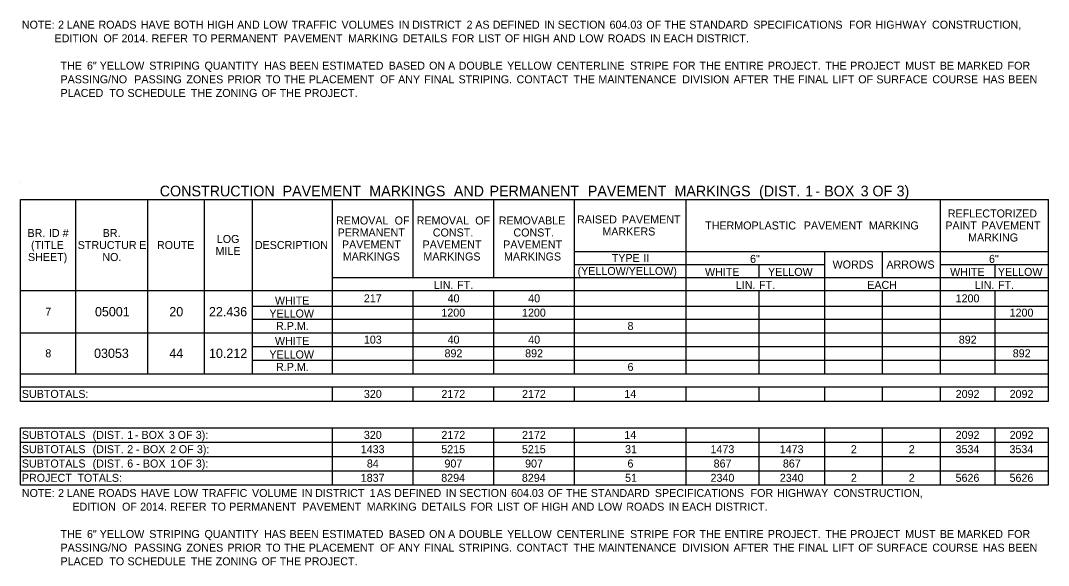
# Model space of a CAD drawing. Extents: x 542596 to 1930787, y -1948294 to 596640.
# Drawn here: x 557797 to 558568, y -1947009 to -1946601 of the extents above; entities that cross this region are included whole.
import ezdxf

# ---------------------------------------------------------------- set-up
doc = ezdxf.new("R2010")
doc.units = 0
doc.layers.add('Default', color=7, linetype='Continuous')

msp = doc.modelspace()

# ---------------------------------------------------------------- linework, layer by layer
at = {"layer": 'Default'}
for p, q in [((557797.21, -1946722.08), (557797.21, -1946722.08)), ((557797.21, -1946734.75), (558567.95, -1946734.75)), ((557797.21, -1946885.88), (557797.21, -1946734.75)), ((557838.65, -1946865.4), (557838.65, -1946734.75)), ((557892.76, -1946865.4), (557892.76, -1946734.75)), ((557935.18, -1946865.4), (557935.18, -1946734.75)), ((557971.25, -1946865.4), (557971.25, -1946734.75)), ((558031.21, -1946865.4), (558031.21, -1946734.75)), ((558091.66, -1946793.25), (558091.66, -1946734.75)), ((558152.11, -1946793.25), (558152.11, -1946734.75)), ((558212.56, -1946865.4), (558212.56, -1946734.75)), ((558296.41, -1946865.4), (558296.41, -1946734.75)), ((558487.03, -1946865.4), (558487.03, -1946734.75)), ((558567.95, -1946875.15), (558567.95, -1946734.75)), ((558212.56, -1946773.75), (558567.95, -1946773.75)), ((558400.25, -1946865.4), (558400.25, -1946773.75)), ((558400.25, -1946865.4), (558400.25, -1946773.75)), ((558443.64, -1946793.25), (558443.64, -1946773.75)), ((558212.56, -1946783.5), (558400.25, -1946783.5)), ((558351.01, -1946793.25), (558351.01, -1946783.5)), ((558487.03, -1946783.5), (558567.95, -1946783.5)), ((558527.98, -1946793.25), (558527.98, -1946783.5)), ((558031.21, -1946793.25), (558567.95, -1946793.25)), ((558212.56, -1946865.4), (558212.56, -1946793.25)), ((558400.25, -1946793.25), (558567.95, -1946793.25)), ((557797.21, -1946803), (558567.95, -1946803)), ((557971.25, -1946803), (558296.41, -1946803)), ((557971.25, -1946865.4), (557971.25, -1946803)), ((558031.21, -1946824.45), (558031.21, -1946803)), ((558091.66, -1946865.4), (558091.66, -1946803)), ((558091.66, -1946865.4), (558091.66, -1946803)), ((558152.11, -1946865.4), (558152.11, -1946803)), ((558152.11, -1946865.4), (558152.11, -1946803)), ((558296.41, -1946865.4), (558296.41, -1946803)), ((558351.01, -1946803), (558567.95, -1946803)), ((558351.01, -1946834.69), (558351.01, -1946803)), ((558351.01, -1946865.4), (558351.01, -1946803)), ((558443.64, -1946865.4), (558443.64, -1946803)), ((558443.64, -1946865.4), (558443.64, -1946803)), ((558487.03, -1946865.4), (558487.03, -1946803)), ((558527.98, -1946865.4), (558527.98, -1946803)), ((558527.98, -1946865.4), (558527.98, -1946803)), ((557971.25, -1946814.7), (558567.95, -1946814.7)), ((557971.25, -1946824.45), (558567.95, -1946824.45)), ((557797.21, -1946834.69), (558567.95, -1946834.69)), ((557971.25, -1946834.69), (558296.41, -1946834.69)), ((558031.21, -1946855.16), (558031.21, -1946834.69)), ((558351.01, -1946834.69), (558567.95, -1946834.69)), ((557971.25, -1946844.93), (558567.95, -1946844.93)), ((557971.25, -1946855.16), (558567.95, -1946855.16)), ((557797.21, -1946865.4), (558567.95, -1946865.4)), ((557797.21, -1946875.15), (558567.95, -1946875.15)), ((557797.21, -1946875.15), (558567.95, -1946875.15)), ((558031.21, -1946885.88), (558031.21, -1946875.15)), ((558031.21, -1946885.88), (558031.21, -1946875.15)), ((558091.66, -1946885.88), (558091.66, -1946875.15)), ((558091.66, -1946885.88), (558091.66, -1946875.15)), ((558152.11, -1946885.88), (558152.11, -1946875.15)), ((558152.11, -1946885.88), (558152.11, -1946875.15)), ((558212.56, -1946885.88), (558212.56, -1946875.15)), ((558212.56, -1946885.88), (558212.56, -1946875.15)), ((558296.41, -1946885.88), (558296.41, -1946875.15)), ((558296.41, -1946885.88), (558296.41, -1946875.15)), ((558351.01, -1946885.88), (558351.01, -1946875.15)), ((558351.01, -1946885.88), (558351.01, -1946875.15)), ((558400.25, -1946885.88), (558400.25, -1946875.15)), ((558400.25, -1946885.88), (558400.25, -1946875.15)), ((558443.64, -1946885.88), (558443.64, -1946875.15)), ((558443.64, -1946885.88), (558443.64, -1946875.15)), ((558487.03, -1946885.88), (558487.03, -1946875.15)), ((558487.03, -1946885.88), (558487.03, -1946875.15)), ((558527.98, -1946885.88), (558527.98, -1946875.15)), ((558527.98, -1946885.88), (558527.98, -1946875.15)), ((558567.95, -1946885.88), (558567.95, -1946875.15)), ((557797.21, -1946885.88), (558567.95, -1946885.88)), ((557797.21, -1946905.86), (558567.95, -1946905.86)), ((557797.21, -1946905.86), (558567.95, -1946905.86)), ((557797.21, -1946948.76), (557797.21, -1946905.86)), ((558031.21, -1946948.76), (558031.21, -1946905.86)), ((558031.21, -1946948.76), (558031.21, -1946905.86)), ((558091.66, -1946948.76), (558091.66, -1946905.86)), ((558091.66, -1946948.76), (558091.66, -1946905.86)), ((558152.11, -1946948.76), (558152.11, -1946905.86)), ((558152.11, -1946948.76), (558152.11, -1946905.86)), ((558212.56, -1946948.76), (558212.56, -1946905.86)), ((558212.56, -1946948.76), (558212.56, -1946905.86)), ((558296.41, -1946948.76), (558296.41, -1946905.86)), ((558296.41, -1946948.76), (558296.41, -1946905.86)), ((558351.01, -1946948.76), (558351.01, -1946905.86)), ((558351.01, -1946948.76), (558351.01, -1946905.86)), ((558400.25, -1946948.76), (558400.25, -1946905.86)), ((558400.25, -1946948.76), (558400.25, -1946905.86)), ((558443.64, -1946948.76), (558443.64, -1946905.86)), ((558443.64, -1946948.76), (558443.64, -1946905.86)), ((558487.03, -1946948.76), (558487.03, -1946905.86)), ((558487.03, -1946948.76), (558487.03, -1946905.86)), ((558527.98, -1946948.76), (558527.98, -1946905.86)), ((558527.98, -1946948.76), (558527.98, -1946905.86)), ((558567.95, -1946948.76), (558567.95, -1946905.86)), ((557797.21, -1946916.59), (558567.95, -1946916.59)), ((557797.21, -1946927.31), (558567.95, -1946927.31)), ((557797.21, -1946938.04), (558567.95, -1946938.04)), ((557797.21, -1946948.76), (558567.95, -1946948.76))]:
    msp.add_line(p, q, dxfattribs=at)

# ---------------------------------------------------------------- texts
for s, height, p in [('NOTE:', 6, (557798.19, -1946606.73)), (' 2', 6, (557823.08, -1946606.73)), (' LANE', 6, (557829.62, -1946606.73)), (' ROADS', 6, (557853.4, -1946606.73)), (' HAVE', 6, (557885.11, -1946606.73)), (' BOTH', 6, (557909.82, -1946606.73)), (' HIGH', 6, (557934.76, -1946606.73)), (' AND', 6, (557957.37, -1946606.73)), (' LOW', 6, (557976.95, -1946606.73)), (' TRAFFIC', 6, (557998.28, -1946606.73)), (' VOLUMES', 6, (558035.67, -1946606.73)), (' IN', 6, (558078.56, -1946606.73)), (' DISTRICT', 6, (558088.58, -1946606.73)), (' 2', 6, (558129.4, -1946606.73)), (' AS', 6, (558135.94, -1946606.73)), (' DEFINED', 6, (558149.01, -1946606.73)), (' IN', 6, (558187.69, -1946606.73)), (' SECTION', 6, (558197.72, -1946606.73)), (' 604.03', 6, (558236.63, -1946606.73)), (' OF', 6, (558264.2, -1946606.73)), (' THE', 6, (558277.79, -1946606.73)), (' STANDARD', 6, (558296.44, -1946606.73)), (' SPECIFICATIONS', 6, (558344.44, -1946606.73)), (' FOR', 6, (558416.21, -1946606.73)), (' HIGHWAY', 6, (558436.12, -1946606.73)), (' CONSTRUCTION,', 6, (558478.44, -1946606.73)), ('           EDITION', 6, (557798.19, -1946616.97)), (' OF', 6, (557857.11, -1946616.97)), (' 2014.', 6, (557870.7, -1946616.97)), (' REFER', 6, (557893.26, -1946616.97)), (' TO', 6, (557923.89, -1946616.97)), (' PERMANENT', 6, (557937.49, -1946616.97)), (' PAVEMENT', 6, (557992.29, -1946616.97)), (' MARKING', 6, (558040.57, -1946616.97)), (' DETAILS', 6, (558081.5, -1946616.97)), (' FOR', 6, (558118.33, -1946616.97)), (' LIST', 6, (558138.24, -1946616.97)), (' OF', 6, (558158.11, -1946616.97)), (' HIGH', 6, (558171.69, -1946616.97)), (' AND', 6, (558194.3, -1946616.97)), (' LOW', 6, (558213.89, -1946616.97)), (' ROADS', 6, (558235.21, -1946616.97)), (' IN', 6, (558266.92, -1946616.97)), (' EACH', 6, (558276.94, -1946616.97)), (' DISTRICT.', 6, (558301.89, -1946616.97)), ('             THE', 6, (557798.19, -1946637.45)), (' 6"', 6, (557844.77, -1946637.45)), (' YELLOW', 6, (557854.34, -1946637.45)), (' STRIPING', 6, (557891.51, -1946637.45)), (' QUANTITY', 6, (557932.91, -1946637.45)), (' HAS', 6, (557977.56, -1946637.45)), (' BEEN', 6, (557996.69, -1946637.45)), (' ESTIMATED', 6, (558021.17, -1946637.45)), (' BASED', 6, (558071.03, -1946637.45)), (' ON', 6, (558101.33, -1946637.45)), (' A', 6, (558115.55, -1946637.45)), (' DOUBLE', 6, (558123.49, -1946637.45)), (' YELLOW', 6, (558159.84, -1946637.45)), (' CENTERLINE', 6, (558197.01, -1946637.45)), (' STRIPE', 6, (558252, -1946637.45)), (' FOR', 6, (558284.17, -1946637.45)), (' THE', 6, (558304.08, -1946637.45)), (' ENTIRE', 6, (558322.73, -1946637.45)), (' PROJECT.', 6, (558355.35, -1946637.45)), (' THE', 6, (558398.41, -1946637.45)), (' PROJECT', 6, (558417.06, -1946637.45)), (' MUST', 6, (558458.35, -1946637.45)), (' BE', 6, (558484.26, -1946637.45)), (' MARKED', 6, (558497.33, -1946637.45)), (' FOR', 6, (558535.08, -1946637.45)), ('             PASSING/NO', 6, (557798.19, -1946647.68)), (' PASSING', 6, (557880.25, -1946647.68)), (' ZONES', 6, (557919.33, -1946647.68)), (' PRIOR', 6, (557950.1, -1946647.68)), (' TO', 6, (557978.87, -1946647.68)), (' THE', 6, (557992.47, -1946647.68)), (' PLACEMENT', 6, (558011.12, -1946647.68)), (' OF', 6, (558064.52, -1946647.68)), (' ANY', 6, (558078.11, -1946647.68)), (' FINAL', 6, (558097.61, -1946647.68)), (' STRIPING.', 6, (558123.4, -1946647.68)), (' CONTACT', 6, (558166.92, -1946647.68)), (' THE', 6, (558209.6, -1946647.68)), (' MAINTENANCE', 6, (558228.25, -1946647.68)), (' DIVISION', 6, (558291.15, -1946647.68)), (' AFTER', 6, (558329.6, -1946647.68)), (' THE', 6, (558359.29, -1946647.68)), (' FINAL', 6, (558377.94, -1946647.68)), (' LIFT', 6, (558403.73, -1946647.68)), (' OF', 6, (558423.12, -1946647.68)), (' SURFACE', 6, (558436.71, -1946647.68)), (' COURSE', 6, (558478.65, -1946647.68)), (' HAS', 6, (558516.4, -1946647.68)), (' BEEN', 6, (558535.53, -1946647.68)), ('             PLACED', 6, (557798.19, -1946657.92)), (' TO', 6, (557861.55, -1946657.92)), (' SCHEDULE', 6, (557875.15, -1946657.92)), (' THE', 6, (557922.68, -1946657.92)), (' ZONING', 6, (557941.33, -1946657.92)), (' OF', 6, (557975.74, -1946657.92)), (' THE', 6, (557989.32, -1946657.92)), (' PROJECT.', 6, (558007.97, -1946657.92)), ('CONSTRUCTION', 8, (557901.59, -1946732.41)), (' PAVEMENT', 8, (557990.74, -1946732.41)), (' MARKINGS', 8, (558055.73, -1946732.41)), (' AND', 8, (558119.14, -1946732.41)), (' PERMANENT', 8, (558145.91, -1946732.41)), (' PAVEMENT', 8, (558219.59, -1946732.41)), (' MARKINGS', 8, (558284.57, -1946732.41)), (' (DIST.', 8, (558347.99, -1946732.41)), (' 1', 8, (558382.61, -1946732.41)), (' BOX', 8, (558396.86, -1946732.41)), (' 3', 8, (558424.18, -1946732.41)), (' OF', 8, (558433.01, -1946732.41)), (' 3)', 8, (558451.12, -1946732.41)), (' -', 8, (558390.12, -1946732.41)), ('REFLECTORIZED', 6, (558492.53, -1946748.25)), ('REMOVAL', 6, (558033.81, -1946753.5)), (' OF', 6, (558075.48, -1946753.5)), ('REMOVAL', 6, (558094.26, -1946753.5)), (' OF', 6, (558135.93, -1946753.5)), ('REMOVABLE', 6, (558155.76, -1946753.5)), ('RAISED', 6, (558214.49, -1946752.75)), (' PAVEMENT', 6, (558245.75, -1946752.75)), ('THERMOPLASTIC', 6, (558310.53, -1946757.25)), (' PAVEMENT', 6, (558382.3, -1946757.25)), (' MARKING', 6, (558431.04, -1946757.25)), ('PAINT', 6, (558490.63, -1946757.25)), (' PAVEMENT', 6, (558515.61, -1946757.25)), ('BR.', 6, (557802.41, -1946762.88)), (' ID', 6, (557816.27, -1946762.88)), (' #', 6, (557826.56, -1946762.88)), ('BR.', 6, (557858.78, -1946762.88)), ('PERMANENT', 6, (558034.97, -1946762.5)), ('CONST.', 6, (558106.34, -1946762.5)), ('CONST.', 6, (558166.79, -1946762.5)), ('MARKERS', 6, (558233.5, -1946761.75)), ('(TITLE', 6, (557805.1, -1946771.88)), ('STRUCTUR', 6, (557840.08, -1946771.88)), ('E', 6, (557886.15, -1946771.88)), ('ROUTE', 6, (557899.5, -1946771.88)), ('LOG', 6, (557944.38, -1946767.38)), ('DESCRIPTION', 6, (557972.92, -1946771.88)), ('PAVEMENT', 6, (558038.23, -1946771.5)), ('PAVEMENT', 6, (558098.68, -1946771.5)), ('PAVEMENT', 6, (558159.13, -1946771.5)), ('MARKING', 6, (558507.72, -1946766.25)), ('SHEET)', 6, (557802.78, -1946780.88)), ('NO.', 6, (557858.54, -1946780.88)), ('MILE', 6, (557943.41, -1946776.38)), ('MARKINGS', 6, (558038.82, -1946780.5)), ('MARKINGS', 6, (558099.27, -1946780.5)), ('MARKINGS', 6, (558159.72, -1946780.5)), ('TYPE', 6, (558240.53, -1946781.63)), (' II', 6, (558262.01, -1946781.63)), ('6"', 6, (558344.22, -1946782.3)), ('WORDS', 6, (558406.08, -1946786.5)), ('ARROWS', 6, (558446.44, -1946786.5)), ('6"', 6, (558523.38, -1946782.3)), ('(YELLOW/YELLOW)', 6, (558214.89, -1946791.38)), ('WHITE', 6, (558310.42, -1946792.05)), ('YELLOW', 6, (558357.71, -1946792.05)), ('WHITE', 6, (558494.2, -1946792.05)), ('YELLOW', 6, (558530.04, -1946792.05)), ('LIN.', 6, (558107.1, -1946801.8)), (' FT.', 6, (558122.35, -1946801.8)), ('LIN.', 6, (558333.54, -1946801.8)), (' FT.', 6, (558348.8, -1946801.8)), ('EACH', 6, (558432.08, -1946801.8)), ('LIN.', 6, (558512.7, -1946801.8)), (' FT.', 6, (558527.95, -1946801.8)), ('217', 6, (558054.64, -1946811.85)), ('40', 6, (558117.43, -1946811.85)), ('40', 6, (558177.88, -1946811.85)), ('1200', 6, (558498.38, -1946811.85)), ('WHITE', 6, (557987.95, -1946813.5)), ('7', 6, (557815.79, -1946821.85)), ('05001', 7, (557853.01, -1946822.35)), ('20', 7, (557908.77, -1946822.35)), ('22.436', 7, (557938.49, -1946822.35)), ('YELLOW', 6, (557983.81, -1946823.25)), ('1200', 6, (558112.77, -1946822.58)), ('1200', 6, (558173.22, -1946822.58)), ('1200', 6, (558538.84, -1946822.58)), ('R.P.M.', 6, (557988.79, -1946832.57)), ('8', 6, (558252.34, -1946832.57)), ('WHITE', 6, (557987.95, -1946843.73)), ('103', 6, (558054.64, -1946842.81)), ('40', 6, (558117.43, -1946842.81)), ('40', 6, (558177.88, -1946842.81)), ('892', 6, (558500.73, -1946842.81)), ('8', 6, (557815.79, -1946853.05)), ('03053', 7, (557852.34, -1946853.55)), ('44', 7, (557908.77, -1946853.55)), ('10.212', 7, (557938.52, -1946853.55)), ('YELLOW', 6, (557983.81, -1946853.96)), ('892', 6, (558115.12, -1946853.05)), ('892', 6, (558175.57, -1946853.05)), ('892', 6, (558541.2, -1946853.05)), ('R.P.M.', 6, (557988.79, -1946863.28)), ('6', 6, (558252.35, -1946863.28)), ('SUBTOTALS:', 6, (557798.19, -1946883.51)), ('320', 6, (558054.65, -1946883.51)), ('2172', 6, (558112.78, -1946883.51)), ('2172', 6, (558173.23, -1946883.51)), ('14', 6, (558249.92, -1946883.51)), ('2092', 6, (558498.39, -1946883.51)), ('2092', 6, (558538.85, -1946883.51)), ('SUBTOTALS', 6, (557798.19, -1946914.23)), (' (DIST.', 6, (557849.01, -1946914.23)), (' 1', 6, (557874.98, -1946914.23)), (' -', 6, (557880.61, -1946914.23)), (' BOX', 6, (557885.67, -1946914.23)), (' 3', 6, (557906.16, -1946914.23)), (' OF', 6, (557912.78, -1946914.23)), (' 3):', 6, (557926.37, -1946914.23)), ('320', 6, (558054.65, -1946914.23)), ('2172', 6, (558112.78, -1946914.23)), ('2172', 6, (558173.23, -1946914.23)), ('14', 6, (558249.92, -1946914.23)), ('2092', 6, (558498.39, -1946914.23)), ('2092', 6, (558538.85, -1946914.23)), ('SUBTOTALS', 6, (557798.19, -1946924.95)), (' (DIST.', 6, (557849.01, -1946924.95)), (' 2', 6, (557874.98, -1946924.95)), (' BOX', 6, (557886.61, -1946924.95)), (' 2', 6, (557907.09, -1946924.95)), (' OF', 6, (557913.66, -1946924.95)), (' 3):', 6, (557927.24, -1946924.95)), ('1433', 6, (558052.3, -1946924.95)), ('5215', 6, (558112.69, -1946924.95)), ('5215', 6, (558173.14, -1946924.95)), ('31', 6, (558250.51, -1946924.95)), ('1473', 6, (558314.57, -1946924.95)), ('1473', 6, (558366.49, -1946924.95)), ('2', 6, (558419.82, -1946924.95)), ('2', 6, (558463.21, -1946924.95)), ('3534', 6, (558498.28, -1946924.95)), ('3534', 6, (558538.74, -1946924.95)), (' -', 6, (557881.55, -1946924.95)), ('SUBTOTALS', 6, (557798.19, -1946935.68)), (' (DIST.', 6, (557849.01, -1946935.68)), (' 6', 6, (557874.98, -1946935.68)), (' -', 6, (557881.67, -1946935.68)), (' BOX', 6, (557886.73, -1946935.68)), (' 1', 6, (557907.22, -1946935.68)), (' OF', 6, (557912.85, -1946935.68)), (' 3):', 6, (557926.43, -1946935.68)), ('84', 6, (558056.87, -1946935.68)), ('907', 6, (558115.08, -1946935.68)), ('907', 6, (558175.53, -1946935.68)), ('6', 6, (558252.31, -1946935.68)), ('867', 6, (558316.91, -1946935.68)), ('867', 6, (558368.83, -1946935.68)), ('PROJECT', 6, (557798.19, -1946946.4)), (' TOTALS:', 6, (557837.61, -1946946.4)), ('1837', 6, (558052.3, -1946946.4)), ('8294', 6, (558112.66, -1946946.4)), ('8294', 6, (558173.11, -1946946.4)), ('51', 6, (558250.51, -1946946.4)), ('2340', 6, (558314.6, -1946946.4)), ('2340', 6, (558366.52, -1946946.4)), ('2', 6, (558419.82, -1946946.4)), ('2', 6, (558463.21, -1946946.4)), ('5626', 6, (558498.33, -1946946.4)), ('5626', 6, (558538.79, -1946946.4)), ('NOTE:', 6, (557798.19, -1946957.8)), (' 2', 6, (557823.08, -1946957.8)), (' LANE', 6, (557829.62, -1946957.8)), (' ROADS', 6, (557853.4, -1946957.8)), (' HAVE', 6, (557885.11, -1946957.8)), (' LOW', 6, (557909.82, -1946957.8)), (' TRAFFIC', 6, (557931.14, -1946957.8)), (' VOLUME', 6, (557968.53, -1946957.8)), (' IN', 6, (558005.82, -1946957.8)), (' DISTRICT', 6, (558015.84, -1946957.8)), (' 1', 6, (558056.66, -1946957.8)), (' AS', 6, (558062.11, -1946957.8)), (' DEFINED', 6, (558075.18, -1946957.8)), (' IN', 6, (558113.86, -1946957.8)), (' SECTION', 6, (558123.89, -1946957.8)), (' 604.03', 6, (558162.79, -1946957.8)), (' OF', 6, (558190.37, -1946957.8)), (' THE', 6, (558203.96, -1946957.8)), (' STANDARD', 6, (558222.61, -1946957.8)), (' SPECIFICATIONS', 6, (558270.61, -1946957.8)), (' FOR', 6, (558342.37, -1946957.8)), (' HIGHWAY', 6, (558362.28, -1946957.8)), (' CONSTRUCTION,', 6, (558404.6, -1946957.8)), ('                 EDITION', 6, (557798.19, -1946968.04)), (' OF', 6, (557871.08, -1946968.04)), (' 2014.', 6, (557884.66, -1946968.04)), (' REFER', 6, (557907.23, -1946968.04)), (' TO', 6, (557937.86, -1946968.04)), (' PERMANENT', 6, (557951.45, -1946968.04)), (' PAVEMENT', 6, (558006.25, -1946968.04)), (' MARKING', 6, (558054.54, -1946968.04)), (' DETAILS', 6, (558095.47, -1946968.04)), (' FOR', 6, (558132.3, -1946968.04)), (' LIST', 6, (558152.21, -1946968.04)), (' OF', 6, (558172.07, -1946968.04)), (' HIGH', 6, (558185.66, -1946968.04)), (' AND', 6, (558208.27, -1946968.04)), (' LOW', 6, (558227.85, -1946968.04)), (' ROADS', 6, (558249.18, -1946968.04)), (' IN', 6, (558280.88, -1946968.04)), (' EACH', 6, (558290.91, -1946968.04)), (' DISTRICT.', 6, (558315.85, -1946968.04)), ('             THE', 6, (557798.19, -1946988.51)), (' 6"', 6, (557844.77, -1946988.51)), (' YELLOW', 6, (557854.34, -1946988.51)), (' STRIPING', 6, (557891.51, -1946988.51)), (' QUANTITY', 6, (557932.91, -1946988.51)), (' HAS', 6, (557977.56, -1946988.51)), (' BEEN', 6, (557996.69, -1946988.51)), (' ESTIMATED', 6, (558021.17, -1946988.51)), (' BASED', 6, (558071.03, -1946988.51)), (' ON', 6, (558101.33, -1946988.51)), (' A', 6, (558115.55, -1946988.51)), (' DOUBLE', 6, (558123.49, -1946988.51)), (' YELLOW', 6, (558159.84, -1946988.51)), (' CENTERLINE', 6, (558197.01, -1946988.51)), (' STRIPE', 6, (558252, -1946988.51)), (' FOR', 6, (558284.17, -1946988.51)), (' THE', 6, (558304.08, -1946988.51)), (' ENTIRE', 6, (558322.73, -1946988.51)), (' PROJECT.', 6, (558355.35, -1946988.51)), (' THE', 6, (558398.41, -1946988.51)), (' PROJECT', 6, (558417.06, -1946988.51)), (' MUST', 6, (558458.35, -1946988.51)), (' BE', 6, (558484.26, -1946988.51)), (' MARKED', 6, (558497.33, -1946988.51)), (' FOR', 6, (558535.08, -1946988.51)), ('             PASSING/NO', 6, (557798.19, -1946998.75)), (' PASSING', 6, (557880.25, -1946998.75)), (' ZONES', 6, (557919.33, -1946998.75)), (' PRIOR', 6, (557950.1, -1946998.75)), (' TO', 6, (557978.87, -1946998.75)), (' THE', 6, (557992.47, -1946998.75)), (' PLACEMENT', 6, (558011.12, -1946998.75)), (' OF', 6, (558064.52, -1946998.75)), (' ANY', 6, (558078.11, -1946998.75)), (' FINAL', 6, (558097.61, -1946998.75)), (' STRIPING.', 6, (558123.4, -1946998.75)), (' CONTACT', 6, (558166.92, -1946998.75)), (' THE', 6, (558209.6, -1946998.75)), (' MAINTENANCE', 6, (558228.25, -1946998.75)), (' DIVISION', 6, (558291.15, -1946998.75)), (' AFTER', 6, (558329.6, -1946998.75)), (' THE', 6, (558359.29, -1946998.75)), (' FINAL', 6, (558377.94, -1946998.75)), (' LIFT', 6, (558403.73, -1946998.75)), (' OF', 6, (558423.12, -1946998.75)), (' SURFACE', 6, (558436.71, -1946998.75)), (' COURSE', 6, (558478.65, -1946998.75)), (' HAS', 6, (558516.4, -1946998.75)), (' BEEN', 6, (558535.53, -1946998.75)), ('             PLACED', 6, (557798.19, -1947008.99)), (' TO', 6, (557861.55, -1947008.99)), (' SCHEDULE', 6, (557875.15, -1947008.99)), (' THE', 6, (557922.68, -1947008.99)), (' ZONING', 6, (557941.33, -1947008.99)), (' OF', 6, (557975.74, -1947008.99)), (' THE', 6, (557989.32, -1947008.99)), (' PROJECT.', 6, (558007.97, -1947008.99))]:
    msp.add_text(s, height=height, dxfattribs=at).set_placement(p)

doc.saveas('drawing.dxf')
